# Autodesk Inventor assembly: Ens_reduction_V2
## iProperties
Shininess: 64.0
Length Units: 11269
Angle Units: 11279
Time Units: 11290
Mass Units: 11283
Length Display Precision: 3
Angle Display Precision: 2
Compacted: True
Created: 2008-04
Part Number: Ens_reduction_V2
Document SubType Name: Assembly
Designer: plup
Density: 0.0
Volumn: 0.0
Area: 0.0
PropertySet Name: Model Information
Control State: 0
Master: False
Checked Out: False
DESIGNATION: Ensemble réduction entrée/sortie
Author: plup
